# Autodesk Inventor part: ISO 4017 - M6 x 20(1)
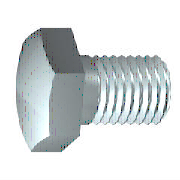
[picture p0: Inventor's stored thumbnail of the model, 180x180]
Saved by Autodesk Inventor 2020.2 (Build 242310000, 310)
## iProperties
Created: 2019-01
Part Number: ISO 4017 - M6 x 20(1)
Material: Stahl, weich
Description: Sechskantschraube
Document SubType Name: Modeling
Standard: DIN EN 24 017
Designer: lutzd
Standards Organization: DIN
Language: de-DE
Size Designation: M6 x 20
Categories: <MemberInstance><Categories><Category DisplayName="Verbindungselemente" InternalName="e4da775c-781d-43d5-af7c-5136215cf5a6" Mnemonic="FSTN"><Category DisplayNam
Density: 7.85 g/cm^3
Appearance: Halbpoliert
IsCustomPart: 0
Author: lutzd
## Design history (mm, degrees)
sketch "Skizze1"
  geometry: L1 (0, 4.44)-(0, 3); L2 (3, 3)-(20, 3); L3 (20, 3)-(20, 0); L4 (20, 0)-(-0.5, 0); L5 (-4.6, 0)-(24.1, 0) reference; L6 (-0.5, 0)-(-0.5, 4.44); L7 (-0.5, 4.44)-(0, 4.44); L8 (3, 3)-(2.386, 3); L9 (2.386, 3)-(0, 3); L10 (0, -0.888)-(0, 5.328) reference
  constraints: 16 end point, 2 collinear, 2 perpendicular, 1 parallel
  dimensions: "d0" = 20 distance between parallel lines of L3 L1 (= NLG); "d1" = 17 distance from line of L2.start L3 (= GEL); "d2" = 6 diameter of L2 L4 (= GD); "d9" = 0.5001 distance between parallel lines of L6 L1 (computed from SD); "d10" = 8.88 diameter of L7 L4 (= SD2); "d13" = 0.61355 distance of L2.start L8.end (computed from GAL); "d14" = 6 diameter of L9 L4 (= BDM)
revolve "Körper" sketch "Skizze1" stored, may be unused: angle "d12" = 90 deg
sketch "Skizze2"
  geometry: L1 (0, 5.774)-(5, 2.887); L2 (5, 2.887)-(5, -2.887); L3 (5, -2.887)-(0, -5.774); L4 (0, -5.774)-(-5, -2.887); L5 (-5, -2.887)-(-5, 2.887); L6 (-5, 2.887)-(0, 5.774); 2 further points
  constraints: 12 end point, 1 coincident, 1 vertical, 11 other
  dimensions: "d11" = 10 distance between parallel lines of L5 L2 (= SW)
extrude "Kopf" join sketch "Skizze2" distance "d3" = 3.5 (= KOH - SD); taper "d4" = 0 deg
sketch "Skizze4"
  geometry: L1 (-4, 5)-(-4, 5.774); L2 (-4, 5.774)-(-3.554, 5.774); L3 (-3.554, 5.774)-(-4, 5); L4 (-4.7, 0)-(0.2, 0) reference; L5 (-0.5, 5.774)-(-4, 5.774) reference; L6 (-4, 2.887)-(-4, 5.774) reference
  constraints: 6 end point, 2 collinear, 1 perpendicular, 1 vertical
  dimensions: "d5" = 30 deg angle of L3 L1 (= ANG1); "d19" = 10 diameter of L1.start L4 (= SW0)
revolve "Fase1" sketch "Skizze4" stored, may be unused: angle "d21" = 90 deg
workplane "Work Plane1"
body "Solid1"
feature "Gewinde" dims "d15" = 17 (= GEL), "d16" = 0
chamfer "Fase2" distance "d6" = 0.61345 (= -0.5 x SPD + 0.5 x GD); stored, may be unused: second distance "d7" = 0.61355 (computed from GUL), angle "d55" = 45 deg
other parameters: "NLG" = 20 [user parameter; used in 1 equation term], "GD" = 6 (= NND) [user parameter; used in 2 equation terms], "BDM" = 6 (= NND) [user parameter; used in 1 equation term], "KOH" = 4 [user parameter; used in 1 equation term], "GEL" = 17 [user parameter; used in 2 equation terms], "SW" = 10 [user parameter; used in 2 equation terms], "SW0" = 10 (= SW) [user parameter; used in 1 equation term], "SPD" = 4.7731 (= NND - 1.2269 x PTC) [user parameter; used in 1 equation term], "SD2" = 8.88 [user parameter; used in 2 equation terms], "SD" = 0.5 [user parameter; used in 2 equation terms], "ANG1" = 30 deg [user parameter; used in 1 equation term], "GAL" = 0.61345 (= 0.61345 x PTC) [user parameter; used in 1 equation term], "GUL" = 0.61345 (= 0.61345 x PTC) [user parameter; used in 1 equation term], "d8" = 0, "RR" = 0.25 [user parameter], "d57" = 0, "d58" = 0, "GD1" = 4.7731 (= THREADDIA - 1.2269 x PTC) [user parameter], "THREADDIA" = 6 [user parameter; used in 1 equation term], "SDH" = 8.88 (= SD2) [user parameter], "SDHG" = 3 [user parameter], "TOA" = 30 deg [user parameter], "PTC" = 1 [user parameter; used in 5 equation terms], "NND" = 6 [user parameter; used in 3 equation terms], "E0" = 11.55 [user parameter]
